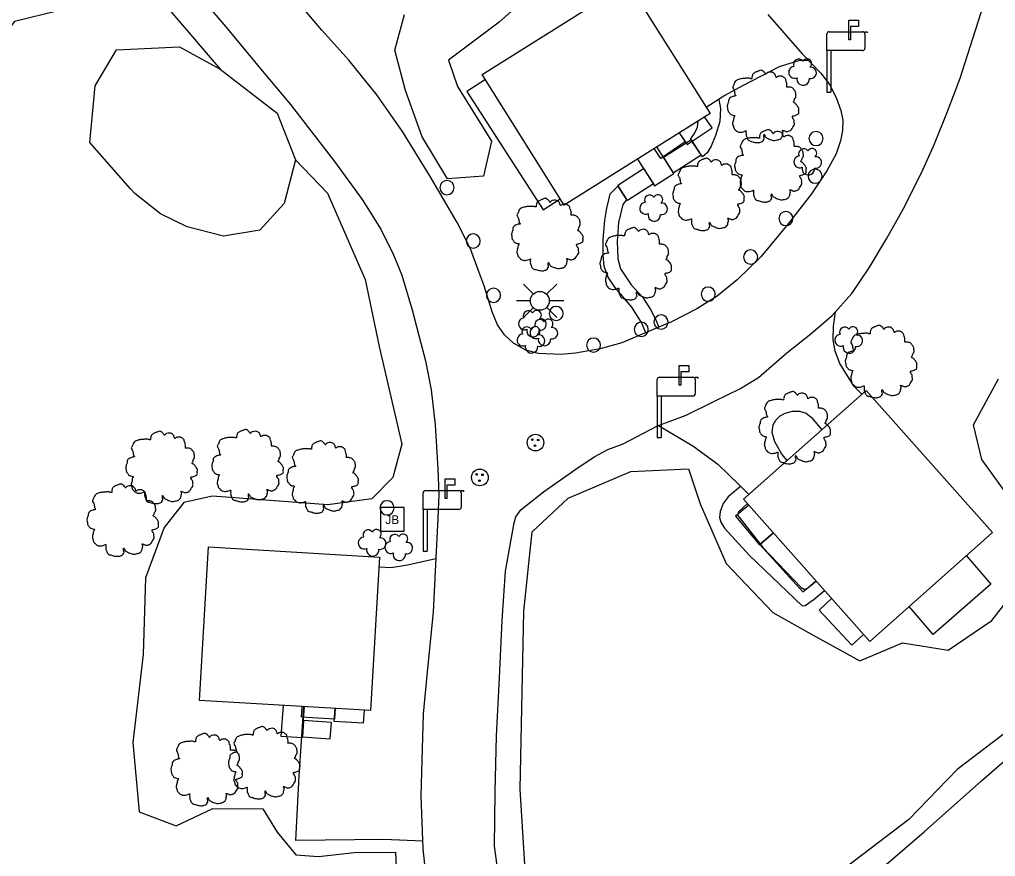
# Model space of a CAD drawing. Extents: x 2160437 to 2172832, y 205694 to 212444.
# Drawn here: x 2171518.5 to 2171725.5, y 206951.1 to 207128.5 of the extents above; entities that cross this region are included whole.
import ezdxf

# ---------------------------------------------------------------- set-up
doc = ezdxf.new("R2010")
doc.units = 0
for name, color, linetype in [('Default', 7, 'Continuous'), ('RD_EX_Bldg', 7, 'Continuous'), ('RD_EX_Bldg_Walls', 7, 'Continuous'), ('RD_EX_BldgApp', 7, 'Continuous'), ('RD_EX_Conc', 7, 'Continuous'), ('RD_EX_DR_Inlet', 7, 'Continuous'), ('RD_EX_Driveway', 7, 'Continuous'), ('RD_EX_H2O_Pond', 7, 'Continuous'), ('RD_EX_Road', 7, 'Continuous'), ('RD_EX_Road_Post', 7, 'Continuous'), ('RD_EX_UT', 7, 'Continuous'), ('RD_EX_VEG', 7, 'Continuous'), ('RD_EX_VEG_ShrubLine', 7, 'Continuous'), ('RD_EX_VEG_TreeLine', 7, 'Continuous')]:
    doc.layers.add(name, color=color, linetype=linetype)

# ---------------------------------------------------------------- blocks, each defined once
blk = doc.blocks.new('MH')
at = {"layer": 'RD_EX_DR_Inlet'}
for centre, radius in [((0, 0), 1.75), ((-0.66, 0.63), 0.175), ((0.56, 0.56), 0.175), ((-0.09, -0.66), 0.175)]:
    blk.add_circle(centre, radius, dxfattribs=at)
blk = doc.blocks.new('POST')
at = {"layer": 'Default'}
for start, end in [(90, 270), (270, 90)]:
    blk.add_arc((0, 0), 0.0417, start, end, dxfattribs=at)
blk = doc.blocks.new('T2')
at = {"layer": 'RD_EX_VEG'}
for points in [[(0.05, 7.21), (-0.25, 7.24), (-0.57, 7.14), (-0.82, 7.04), (-1.05, 6.96), (-1.27, 6.86), (-1.57, 6.69), (-1.8, 6.49), (-1.92, 6.24), (-1.97, 6.01), (-2.02, 5.74), (-2.02, 5.56), (-2.15, 5.54), (-2.3, 5.56), (-2.55, 5.64), (-2.8, 5.64), (-3.05, 5.64), (-3.4, 5.61), (-3.75, 5.61), (-4.02, 5.56), (-4.35, 5.51), (-4.72, 5.39), (-5.07, 5.26), (-5.37, 5.01), (-5.62, 4.54), (-5.75, 4.19), (-5.9, 3.94), (-5.75, 3.49), (-5.57, 3.14), (-5.55, 2.94), (-5.47, 2.52), (-5.37, 2.29), (-5.25, 2.09), (-5.32, 2.07), (-5.7, 2.02), (-6, 1.92), (-6.42, 1.69), (-6.64, 1.47), (-6.74, 1.14), (-6.77, 0.79), (-6.87, 0.59), (-6.94, 0.32), (-6.97, 0.24), (-7.02, -0.08), (-6.92, -0.53), (-6.89, -0.88), (-6.77, -1.11), (-6.62, -1.28), (-6.44, -1.53), (-6.05, -1.76), (-5.72, -1.86), (-5.52, -1.88), (-5.7, -2.38), (-5.75, -2.73), (-5.87, -3.13), (-5.87, -3.21), (-5.92, -3.68), (-5.77, -4.01), (-5.7, -4.38), (-5.52, -4.61), (-5.25, -4.91), (-4.92, -5.13), (-4.42, -5.26), (-4.02, -5.23), (-3.45, -5.06), (-3.2, -4.98), (-3.22, -5.16), (-3.2, -5.53), (-3.2, -5.96), (-3.05, -6.28), (-2.95, -6.56), (-2.8, -6.81), (-2.47, -7.03), (-2.07, -7.11), (-1.65, -7.26), (-1.2, -7.33), (-0.7, -7.36), (-0.1, -7.21), (0.18, -7.08), (0.28, -6.91), (0.48, -6.53), (0.43, -6.31), (0.45, -5.71), (0.55, -5.88), (0.73, -6.23), (1.23, -6.53), (1.63, -6.71), (2.1, -6.86), (2.4, -6.93), (2.88, -6.86), (3.25, -6.78), (3.63, -6.66), (3.93, -6.38), (4.1, -6.11), (4.15, -5.83), (4.23, -5.46), (4.28, -5.28)], [(4.28, -5.28), (4.2, -5.11), (4.15, -4.86), (4.23, -4.88), (4.4, -4.93), (4.68, -5.06), (4.9, -5.13), (5.23, -5.11), (5.5, -5.01), (5.95, -4.73), (6.22, -4.26), (6.5, -3.86), (6.57, -3.53), (6.52, -3.31), (6.5, -2.81), (6.3, -2.56), (6.25, -2.43), (6.15, -2.03), (6.22, -1.98), (6.5, -1.93), (6.87, -1.81), (7.15, -1.68), (7.37, -1.51), (7.45, -1.28), (7.42, -0.88), (7.47, -0.48), (7.4, -0.33), (7.3, -0.18), (7.22, 0.02), (7.07, 0.17), (6.97, 0.32), (6.87, 0.42), (6.75, 0.57), (6.57, 0.69), (6.42, 0.74), (6.37, 0.89), (6.52, 1.09), (6.57, 1.19), (6.6, 1.42), (6.82, 1.77), (6.87, 2.17), (6.82, 2.59), (6.77, 2.87), (6.62, 3.14), (6.42, 3.39), (6.3, 3.56), (6.12, 3.69), (5.8, 3.81), (5.55, 3.86), (5.2, 3.86), (5, 3.91), (5.03, 3.96), (5.03, 4.11), (5.03, 4.39), (4.95, 4.84), (4.8, 5.34), (4.8, 5.36), (4.7, 5.61), (4.48, 5.81), (4.3, 5.91), (4.1, 6.04), (3.85, 6.06), (3.55, 6.06), (3.28, 6.01), (3.08, 5.91), (2.9, 5.79), (2.83, 5.94), (2.73, 6.24), (2.68, 6.39), (2.53, 6.56), (2.3, 6.76), (1.85, 6.89), (1.23, 6.81), (0.93, 6.61), (0.78, 6.44), (0.73, 6.56), (0.53, 6.76), (0.43, 6.94), (0.25, 7.06), (0.1, 7.16), (0, 7.21)]]:
    blk.add_spline(points, degree=3, dxfattribs=at)

msp = doc.modelspace()

# ---------------------------------------------------------------- linework, layer by layer
at = {"layer": 'RD_EX_Bldg'}
for points in [[(2171647.59, 207136.3), (2171665, 207108.58), (2171634.09, 207089.16), (2171616.67, 207116.87)], [(2171672.11, 207026.79), (2171698.12, 207049.87), (2171724.88, 207019.71), (2171698.87, 206996.64)], [(2171594.91, 207014.53), (2171592.99, 206982), (2171556.7, 206984.13), (2171558.61, 207016.67)]]:
    msp.add_lwpolyline(points, close=True, dxfattribs=at)
at = {"layer": 'RD_EX_Bldg_Walls'}
for points in [[(2171695.04, 206995.85), (2171688.13, 207003.29), (2171690.78, 207005.75)], [(2171697.53, 206998.15), (2171695.04, 206995.85)]]:
    msp.add_lwpolyline(points, dxfattribs=at)
at = {"layer": 'RD_EX_BldgApp'}
for p, q in [((2171694.43, 207128.38), (2171696.49, 207128.38)), ((2171694.43, 207124.19), (2171694.43, 207128.38)), ((2171696.49, 207128.38), (2171696.49, 207127.03)), ((2171690.29, 207125.9), (2171697.36, 207125.9)), ((2171696.49, 207127.03), (2171694.81, 207127.03)), ((2171694.81, 207127.03), (2171694.81, 207124.19)), ((2171697.86, 207125.4), (2171697.86, 207125.9)), ((2171697.86, 207125.9), (2171698.36, 207125.9)), ((2171698.36, 207125.9), (2171698.36, 207125.65)), ((2171689.79, 207121.9), (2171689.79, 207125.4)), ((2171694.81, 207124.19), (2171694.43, 207124.19)), ((2171697.86, 207125.4), (2171697.86, 207122.4)), ((2171689.79, 207121.9), (2171689.79, 207113.08)), ((2171697.36, 207121.9), (2171689.79, 207121.9)), ((2171690.63, 207121.9), (2171690.63, 207113.08)), ((2171689.79, 207113.08), (2171690.63, 207113.08)), ((2171658.45, 207055.15), (2171660.51, 207055.15)), ((2171658.45, 207050.96), (2171658.45, 207055.15)), ((2171660.51, 207053.8), (2171658.83, 207053.8)), ((2171658.83, 207053.8), (2171658.83, 207050.96)), ((2171660.51, 207055.15), (2171660.51, 207053.8)), ((2171653.81, 207048.67), (2171653.81, 207052.17)), ((2171654.31, 207052.67), (2171661.38, 207052.67)), ((2171661.88, 207052.17), (2171661.88, 207052.67)), ((2171661.88, 207052.67), (2171662.38, 207052.67)), ((2171661.88, 207052.17), (2171661.88, 207049.17)), ((2171662.38, 207052.67), (2171662.38, 207052.42)), ((2171658.83, 207050.96), (2171658.45, 207050.96)), ((2171653.81, 207048.67), (2171653.81, 207039.85)), ((2171661.38, 207048.67), (2171653.81, 207048.67)), ((2171654.65, 207048.67), (2171654.65, 207039.85)), ((2171653.81, 207039.85), (2171654.65, 207039.85)), ((2171608.8, 207031.11), (2171610.85, 207031.11)), ((2171608.8, 207026.92), (2171608.8, 207031.11)), ((2171610.85, 207031.11), (2171610.85, 207029.76)), ((2171604.65, 207028.63), (2171611.72, 207028.63)), ((2171610.85, 207029.76), (2171609.18, 207029.76)), ((2171609.18, 207029.76), (2171609.18, 207026.92)), ((2171612.22, 207028.13), (2171612.22, 207028.63)), ((2171612.22, 207028.63), (2171612.72, 207028.63)), ((2171612.72, 207028.63), (2171612.72, 207028.38)), ((2171604.15, 207024.63), (2171604.15, 207028.13)), ((2171609.18, 207026.92), (2171608.8, 207026.92)), ((2171612.22, 207028.13), (2171612.22, 207025.13)), ((2171604.15, 207024.63), (2171604.15, 207015.81)), ((2171611.72, 207024.63), (2171604.15, 207024.63)), ((2171604.99, 207024.63), (2171604.99, 207015.81)), ((2171604.15, 207015.81), (2171604.99, 207015.81))]:
    msp.add_line(p, q, dxfattribs=at)
for points in [[(2171617.36, 207115.77), (2171613.43, 207113.23)], [(2171613.43, 207113.23), (2171629.61, 207088.15), (2171633.24, 207090.5)], [(2171660.12, 207101.99), (2171665.42, 207105.54), (2171663.86, 207107.86)], [(2171658.46, 207104.47), (2171659.74, 207102.56), (2171654.54, 207099.07), (2171653.15, 207101.13)], [(2171658.46, 207104.47), (2171660.12, 207101.99)], [(2171653.25, 207093.26), (2171657.32, 207095.85), (2171653.72, 207101.49)], [(2171649.63, 207098.92), (2171653.25, 207093.26)], [(2171673.2, 207025.57), (2171670.37, 207023.19)], [(2171670.37, 207023.19), (2171675.49, 207017.14), (2171678.46, 207019.64)], [(2171678.46, 207019.64), (2171675.56, 207017.2), (2171684.68, 207007.15), (2171687.5, 207009.45)], [(2171719.36, 207014.82), (2171724.58, 207008.8)], [(2171724.58, 207008.8), (2171712.29, 206998.15), (2171707.2, 207004.02)], [(2171574.45, 206983.09), (2171574, 206976.57), (2171578.52, 206976.26)], [(2171585.48, 206982.44), (2171585.34, 206980.16), (2171578.38, 206980.57), (2171578.52, 206982.85)], [(2171578.52, 206976.26), (2171578.97, 206982.82)], [(2171591.46, 206979.32), (2171585.31, 206979.69), (2171585.48, 206982.44)], [(2171591.63, 206982.08), (2171591.46, 206979.32)]]:
    msp.add_lwpolyline(points, dxfattribs=at)
for points in [[(2171655.15, 207099.25), (2171657.21, 207096.02), (2171663.11, 207099.8), (2171661.05, 207103.02)], [(2171650.92, 207096.9), (2171653, 207093.65), (2171647.51, 207090.14), (2171645.43, 207093.38)], [(2171578.76, 206979.9), (2171578.53, 206976.44), (2171584.45, 206976.03), (2171584.69, 206979.49)]]:
    msp.add_lwpolyline(points, close=True, dxfattribs=at)
for centre, start, end in [((2171690.29, 207125.4), 90, 180), ((2171697.36, 207125.4), 360, 90), ((2171697.36, 207122.4), 270, 0), ((2171654.31, 207052.17), 90, 180), ((2171661.38, 207052.17), 360, 90), ((2171661.38, 207049.17), 270, 0), ((2171604.65, 207028.13), 90, 180), ((2171611.72, 207028.13), 360, 90), ((2171611.72, 207025.13), 270, 0)]:
    msp.add_arc(centre, 0.5, start, end, dxfattribs=at)
at = {"layer": 'RD_EX_Conc'}
for points in [[(2171666.85, 207111.57), (2171667.25, 207109.65), (2171667.1, 207106.86), (2171666.18, 207103.89), (2171665.25, 207101.63), (2171664.41, 207100.25), (2171663.41, 207099.39), (2171660.86, 207103.17), (2171661.71, 207104.34), (2171662.33, 207105.71), (2171662.45, 207106.98)], [(2171651.39, 207062.07), (2171650.48, 207064.27), (2171648.38, 207067.5), (2171644.84, 207071.78), (2171643.45, 207073.75), (2171642.56, 207076.15), (2171642.3, 207078.55), (2171642.31, 207081.85), (2171642.72, 207085.99), (2171643.09, 207088.51), (2171643.55, 207090.29), (2171643.83, 207091.53), (2171645.42, 207093.18), (2171647.3, 207090.29), (2171646.49, 207089.25), (2171645.61, 207085.5), (2171645.28, 207081.53), (2171645.41, 207077.75), (2171646.03, 207075.61), (2171648.29, 207072.25), (2171650.74, 207069.58), (2171652.38, 207067), (2171653.51, 207064.82), (2171654.16, 207063.26)], [(2171671.51, 207029.58), (2171668.85, 207027.27), (2171667.78, 207025.9), (2171667.14, 207024.22), (2171666.99, 207022.91), (2171667.28, 207021.95), (2171668.1, 207020.67), (2171673.38, 207014.9), (2171684.52, 207004.22), (2171685.15, 207004.26), (2171687.09, 207005.64), (2171689.25, 207007.48)], [(2171672.94, 207025.86), (2171672.01, 207025.06), (2171671.03, 207024.14), (2171670.85, 207023.43), (2171671.15, 207022.99), (2171676.2, 207016.56), (2171684.3, 207008.09), (2171685.05, 207007.63), (2171685.73, 207008), (2171687.44, 207009.52)]]:
    msp.add_lwpolyline(points, dxfattribs=at)
at = {"layer": 'RD_EX_DR_Inlet'}
msp.add_line((2171600.11, 207020.05), (2171600.11, 207025.05), dxfattribs=at)
msp.add_lwpolyline([(2171600.11, 207020.05), (2171600.11, 207025.05), (2171595.11, 207025.05), (2171595.11, 207020.05)], close=True, dxfattribs=at)
at = {"layer": 'RD_EX_Driveway'}
for points in [[(2171685.9, 207119.81), (2171683.95, 207119.84), (2171679.68, 207118.5), (2171671.9, 207114.44), (2171668.11, 207112.4), (2171664.21, 207109.84)], [(2171697.18, 207049.04), (2171695.55, 207050.71), (2171692.52, 207055.56), (2171691.52, 207058.18), (2171691.11, 207060.6), (2171691.18, 207063.46), (2171691.63, 207066.52)], [(2171681.39, 207035.02), (2171680.23, 207036.36), (2171678.72, 207038.98), (2171678.21, 207040.95), (2171678.37, 207042.57), (2171678.95, 207043.55), (2171679.9, 207044.46), (2171680.96, 207045.01), (2171682.47, 207045.46), (2171684, 207045.44), (2171685.36, 207045.02), (2171686.51, 207044.11), (2171688.68, 207041.5)], [(2171654.06, 207042.43), (2171661.33, 207038.14), (2171666.68, 207034.21), (2171671.28, 207029.81), (2171673.26, 207027.81)], [(2171606.81, 207014.18), (2171600.81, 207012.84), (2171597.34, 207012.27), (2171594.79, 207012.41)], [(2171604.05, 206954.28), (2171595.83, 206954.67), (2171577.12, 206954.44), (2171577.88, 206968.14), (2171578.83, 206982.83)]]:
    msp.add_lwpolyline(points, dxfattribs=at)
at = {"layer": 'RD_EX_H2O_Pond'}
msp.add_lwpolyline([(2171726.78, 206857.6), (2171722.01, 206854.96), (2171715.08, 206851.95), (2171709.64, 206850.39), (2171701.14, 206850.03), (2171695.18, 206850.54), (2171691.81, 206850.92), (2171688.01, 206852.79), (2171682.46, 206856.87), (2171675.57, 206863.74), (2171666.7, 206875.65), (2171663.12, 206883.49), (2171661.55, 206894.98), (2171662.66, 206902.49), (2171664.78, 206908.42), (2171668.55, 206913.75), (2171673.33, 206920.6), (2171679.52, 206928.28), (2171684.61, 206933.61), (2171693.81, 206942.02), (2171710.44, 206956.31), (2171722.6, 206967.07), (2171736.13, 206978.92)], dxfattribs=at)
at = {"layer": 'RD_EX_Road'}
for points in [[(2171553.25, 207137.55), (2171562.31, 207126.95), (2171570.11, 207117.52), (2171576, 207110.52), (2171585.35, 207098.38), (2171591.23, 207090.31), (2171595.2, 207084.02), (2171597.85, 207078.63), (2171599.6, 207074.32), (2171601.85, 207066.97), (2171603.21, 207061.49), (2171604.64, 207056.14), (2171605.82, 207049.98), (2171606.69, 207042.55), (2171607.29, 207033.26), (2171607.5, 207027.88), (2171607.28, 207022.7), (2171606.74, 207012.97), (2171606.26, 207002.88), (2171605.05, 206990.92), (2171604.17, 206981.27), (2171603.86, 206971.38), (2171603.64, 206963.91), (2171604.12, 206952.7), (2171605.64, 206938.11)], [(2171677.29, 207129.57), (2171684.52, 207121.22), (2171688.5, 207117.13), (2171688.5, 207117.13), (2171690.35, 207114.73), (2171691.74, 207111.96), (2171692.77, 207109.18), (2171693.17, 207107.13), (2171693.09, 207104.96), (2171692.68, 207102.76), (2171691.74, 207100.05), (2171689.75, 207096.39), (2171686.5, 207091.52), (2171681.59, 207085.22), (2171675.77, 207078.2), (2171670.74, 207073.33), (2171666.48, 207069.87), (2171662.17, 207067.18), (2171656.86, 207064.42), (2171652.33, 207062.47), (2171646.32, 207059.93), (2171641.7, 207058.68), (2171636.43, 207057.75), (2171633.36, 207057.49), (2171628.6, 207057.69), (2171625.91, 207058.4), (2171623.28, 207059.86), (2171621.41, 207061.66), (2171619.92, 207063.77), (2171618.79, 207066.55), (2171617.1, 207072.05), (2171615.85, 207075.45), (2171614.17, 207079.9), (2171611.36, 207085.46), (2171605.56, 207095.36), (2171599.79, 207104.78), (2171594.34, 207112.54), (2171588.39, 207119.85), (2171582.69, 207126.23), (2171576.25, 207133.86)], [(2171620.49, 206944.52), (2171619.3, 206953.25), (2171619.46, 206964.7), (2171619.74, 206976.61), (2171620.37, 206988.91), (2171620.88, 207001.12), (2171621.65, 207011.51), (2171623.45, 207021.77), (2171623.83, 207023.04), (2171624.88, 207024.54), (2171629.65, 207028.34), (2171637, 207033.49), (2171640.56, 207035.84), (2171643.33, 207037.33), (2171646.58, 207038.53), (2171653.87, 207042.36), (2171659.95, 207044.59), (2171666.11, 207047.65), (2171671.3, 207050.21), (2171675.29, 207052.64), (2171681.28, 207057.83), (2171686.37, 207061.84), (2171690.93, 207065.73), (2171695.09, 207070.4), (2171698.78, 207075.89), (2171702.4, 207081.99), (2171705.97, 207088.27), (2171709.94, 207096.17), (2171712.58, 207102.14), (2171715.34, 207109.02), (2171718.07, 207116.1), (2171720.73, 207124.47), (2171723.58, 207133.37)]]:
    msp.add_lwpolyline(points, dxfattribs=at)
at = {"layer": 'RD_EX_UT'}
for p, q in [((2171625.42, 207072.4), (2171627.52, 207070.31)), ((2171630.33, 207070.24), (2171632.5, 207072.4)), ((2171626.89, 207068.87), (2171623.96, 207068.87)), ((2171633.96, 207068.87), (2171630.89, 207068.87)), ((2171625.42, 207065.33), (2171627.5, 207067.41)), ((2171630.35, 207067.48), (2171632.5, 207065.33))]:
    msp.add_line(p, q, dxfattribs=at)
msp.add_circle((2171628.89, 207068.85), 2, dxfattribs=at)
at = {"layer": 'RD_EX_VEG'}
for centre, radius, start, end in [((2171683.78, 207119.02), 1.08, 34.9763, 204.756), ((2171685.55, 207119.17), 0.995, 308.7626, 152.0467), ((2171682.94, 207117.31), 1.26, 96.4518, 294.734), ((2171686.34, 207117.19), 1.22, 256.5667, 98.1046), ((2171684.75, 207115.87), 1.32, 166.8827, 5.7589), ((2171684.87, 207100.02), 1.08, 34.9763, 204.756), ((2171686.64, 207100.17), 0.995, 308.7626, 152.0467), ((2171684.03, 207098.31), 1.26, 96.4518, 294.734), ((2171687.43, 207098.19), 1.22, 256.5667, 98.1046), ((2171685.84, 207096.87), 1.32, 166.8827, 5.7589), ((2171652.19, 207090.21), 1.08, 34.9763, 204.756), ((2171653.96, 207090.36), 0.995, 308.7626, 152.0467), ((2171651.35, 207088.5), 1.26, 96.4518, 294.734), ((2171654.75, 207088.38), 1.22, 256.5667, 98.1046), ((2171653.16, 207087.06), 1.32, 166.8827, 5.7589), ((2171626.47, 207065.69), 1.08, 34.9763, 204.756), ((2171628.24, 207065.84), 0.995, 308.7626, 152.0467), ((2171625.63, 207063.98), 1.26, 96.4518, 294.734), ((2171628.92, 207063.82), 1.08, 34.9763, 204.756), ((2171629.03, 207063.86), 1.22, 256.5667, 98.1046), ((2171630.69, 207063.97), 0.995, 308.7626, 152.0467), ((2171625.33, 207060.54), 1.26, 96.4518, 294.734), ((2171626.17, 207062.25), 1.08, 34.9763, 204.756), ((2171627.44, 207062.54), 1.32, 166.8827, 5.7589), ((2171628.08, 207062.11), 1.26, 96.4518, 294.734), ((2171627.94, 207062.4), 0.995, 308.7626, 152.0467), ((2171631.48, 207061.99), 1.22, 256.5667, 98.1046), ((2171692.73, 207060.51), 1.26, 96.4518, 294.734), ((2171693.57, 207062.22), 1.08, 34.9763, 204.756), ((2171695.34, 207062.37), 0.995, 308.7626, 152.0467), ((2171628.73, 207060.42), 1.22, 256.5667, 98.1046), ((2171629.89, 207060.67), 1.32, 166.8827, 5.7589), ((2171696.13, 207060.39), 1.22, 256.5667, 98.1046), ((2171627.14, 207059.1), 1.32, 166.8827, 5.7589), ((2171694.54, 207059.07), 1.32, 166.8827, 5.7589), ((2171592.49, 207019.22), 1.08, 34.9763, 204.756), ((2171594.26, 207019.37), 0.995, 308.7626, 152.0467), ((2171591.65, 207017.51), 1.26, 96.4518, 294.734), ((2171595.05, 207017.39), 1.22, 256.5667, 98.1046), ((2171598.13, 207018.27), 1.08, 34.9763, 204.756), ((2171599.9, 207018.42), 0.995, 308.7626, 152.0467), ((2171593.46, 207016.07), 1.32, 166.8827, 5.7589), ((2171597.29, 207016.56), 1.26, 96.4518, 294.734), ((2171600.69, 207016.44), 1.22, 256.5667, 98.1046), ((2171599.1, 207015.12), 1.32, 166.8827, 5.7589)]:
    msp.add_arc(centre, radius, start, end, dxfattribs=at)
at = {"layer": 'RD_EX_VEG_ShrubLine'}
for points in [[(2171532.6, 207154.5), (2171539.69, 207144.82), (2171550.96, 207129.8), (2171561.12, 207117.96)], [(2171577.09, 207098.75), (2171583.89, 207091.69), (2171591.82, 207073.39), (2171594.81, 207059.19), (2171599.61, 207038.48), (2171597.75, 207031.42), (2171593.29, 207026.85), (2171583.94, 207025.59), (2171559.46, 207027.44), (2171553.38, 207026.07), (2171549.24, 207020.81), (2171545.29, 207010.12), (2171544.77, 206993.89), (2171542.6, 206975.22), (2171543.94, 206960.49), (2171551.78, 206957.53), (2171559.57, 206961.21), (2171570.13, 206961.17), (2171573.2, 206956.22), (2171577.18, 206951.4), (2171581.93, 206951.03), (2171589.51, 206951.93), (2171598.28, 206951.95), (2171598.67, 206943.97)]]:
    msp.add_lwpolyline(points, dxfattribs=at)
at = {"layer": 'RD_EX_VEG_TreeLine'}
for points in [[(2171474.7, 207108.12), (2171459.43, 207112.36), (2171453.09, 207127.15), (2171458.48, 207141.66), (2171474.91, 207153.67), (2171485.5, 207155.53), (2171493.08, 207151.09), (2171502.51, 207155.09), (2171516.48, 207162.45), (2171527.21, 207161.36), (2171532.6, 207154.5), (2171529.45, 207147.18), (2171534.81, 207141.4), (2171536.01, 207132.62), (2171517.46, 207128.1), (2171506.13, 207113), (2171497.21, 207101.28), (2171490.38, 207100.15), (2171482.44, 207102.63), (2171478.6, 207107.07), (2171475.14, 207107.7)], [(2171542.08, 207092.61), (2171533.46, 207102.46), (2171534.6, 207114.45), (2171539.08, 207122.11), (2171552.49, 207122.68), (2171561.12, 207117.96), (2171573.2, 207108.66), (2171577.09, 207098.75), (2171574.65, 207089.5), (2171569.49, 207083.85), (2171561.84, 207082.56), (2171554.08, 207084.53), (2171548.43, 207087.34), (2171543.03, 207091.64)]]:
    msp.add_lwpolyline(points, close=True, dxfattribs=at)
for points in [[(2171627.58, 207134.5), (2171620.31, 207127.91), (2171609.53, 207119.86), (2171611.45, 207114.28), (2171618.65, 207102.73), (2171616.93, 207095.29), (2171609.3, 207094.74), (2171603.97, 207103.6), (2171600.39, 207113.48), (2171598.12, 207122.01), (2171600.22, 207129.6)], [(2171730.32, 207024.54), (2171722.63, 207035.24), (2171720.87, 207042.57), (2171726.2, 207052.3)], [(2171626.19, 206941.37), (2171624.72, 206965.35), (2171625.5, 207003.06), (2171627.25, 207019.89), (2171634.93, 207027.05), (2171648.22, 207032.69), (2171660.46, 207033.27), (2171662.92, 207025.83), (2171668.41, 207013.14), (2171678.31, 207002.81), (2171686.9, 206998.01), (2171696.77, 206992.5), (2171705.81, 206996.36), (2171715.47, 206994.81), (2171724.78, 207001.11), (2171729.74, 207007.48)], [(2171732.86, 206981.25), (2171717.42, 206969.53), (2171707.16, 206958.86), (2171690.91, 206946.55)]]:
    msp.add_lwpolyline(points, dxfattribs=at)

# ---------------------------------------------------------------- block references
at = {"layer": 'RD_EX_DR_Inlet', "xscale": 1.0079999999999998, "yscale": 1.0079999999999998}
for p in [(2171627.98, 207038.8), (2171616.18, 207031.41)]:
    msp.add_blockref('MH', p, dxfattribs=at)
at = {"layer": 'RD_EX_Road_Post', "xscale": 36, "yscale": 36}
for p in [(2171687.48, 207103.27), (2171687.29, 207095.28), (2171609.21, 207092.86), (2171681.08, 207086.31), (2171614.77, 207081.54), (2171673.61, 207078.14), (2171619.07, 207070.04), (2171664.61, 207070.27), (2171632.38, 207066.18), (2171654.6, 207064.36), (2171650.41, 207062.81), (2171640.29, 207059.47), (2171596.49, 207024.97)]:
    msp.add_blockref('POST', p, dxfattribs=at)
at = {"layer": 'RD_EX_VEG', "xscale": 1.0499999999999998, "yscale": 1.0499999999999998}
for p in [(2171676, 207110.13), (2171677.58, 207097.53), (2171664.44, 207091.5), (2171630.25, 207082.96), (2171649.01, 207076.79), (2171701.05, 207056.05), (2171682.73, 207042.03), (2171548.45, 207033.59), (2171566.69, 207033.97), (2171582.59, 207031.57), (2171540.21, 207022.42), (2171558, 206969.55), (2171570.21, 206970.99)]:
    msp.add_blockref('T2', p, dxfattribs=at)

# ---------------------------------------------------------------- texts
at = {"layer": 'RD_EX_DR_Inlet'}
msp.add_text('JB', height=1.875, dxfattribs=at).set_placement((2171596.14, 207021.53))

doc.saveas('drawing.dxf')
